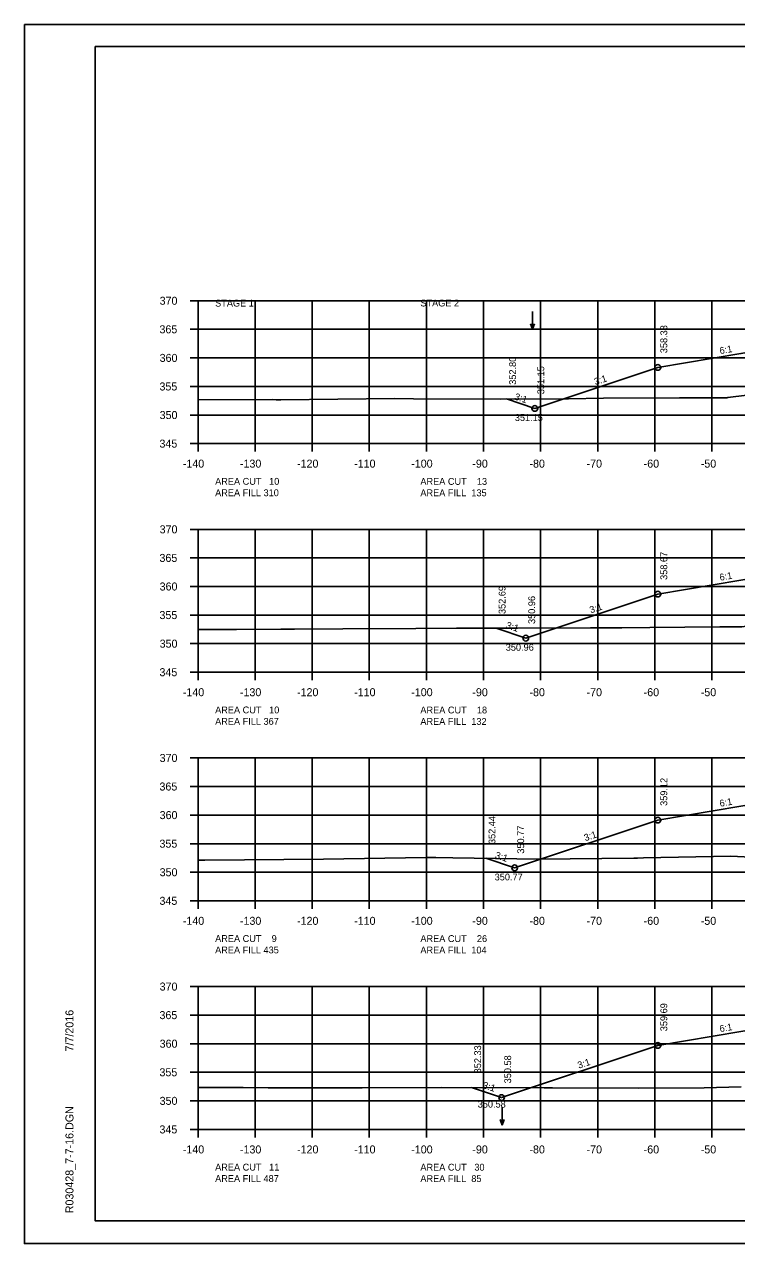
# Model space of a CAD drawing. Extents: x 1374859 to 1376773, y 382242 to 389804.
# Drawn here: x 1375964.2 to 1376088.9, y 386295.2 to 386508.5 of the extents above; entities that cross this region are included whole.
import ezdxf

# ---------------------------------------------------------------- set-up
doc = ezdxf.new("R2010")
doc.units = 0
for name, color, linetype in [('R_Axis', 7, 'Continuous'), ('R_Axis Annot', 7, 'Continuous'), ('R_Border', 7, 'Continuous'), ('R_Exist Surface', 7, 'Continuous'), ('R_Fin Surface', 7, 'Continuous'), ('R_Grid', 7, 'Continuous'), ('R_No Plot', 7, 'Continuous'), ('R_Water Annot', 7, 'Continuous'), ('R_Xsect Elev', 7, 'Continuous'), ('R_Xsect Slope', 7, 'Continuous')]:
    doc.layers.add(name, color=color, linetype=linetype)

msp = doc.modelspace()

# ---------------------------------------------------------------- linework, layer by layer
at = {"layer": 'R_Axis'}
for p, q in [((1375993.17, 386460.14), (1375994.57, 386460.14)), ((1375994.57, 386435.14), (1375994.57, 386460.14)), ((1375993.17, 386455.14), (1375994.57, 386455.14)), ((1375993.17, 386450.14), (1375994.57, 386450.14)), ((1375993.17, 386445.14), (1375994.57, 386445.14)), ((1375993.17, 386440.14), (1375994.57, 386440.14)), ((1375993.17, 386435.14), (1375994.57, 386435.14)), ((1375994.57, 386435.14), (1376274.57, 386435.14)), ((1375994.57, 386433.74), (1375994.57, 386435.14)), ((1376004.57, 386433.74), (1376004.57, 386435.14)), ((1376014.57, 386433.74), (1376014.57, 386435.14)), ((1376024.57, 386433.74), (1376024.57, 386435.14)), ((1376034.57, 386433.74), (1376034.57, 386435.14)), ((1376044.57, 386433.74), (1376044.57, 386435.14)), ((1376054.57, 386433.74), (1376054.57, 386435.14)), ((1376064.57, 386433.74), (1376064.57, 386435.14)), ((1376074.57, 386433.74), (1376074.57, 386435.14)), ((1376084.57, 386433.74), (1376084.57, 386435.14)), ((1375993.17, 386420.14), (1375994.57, 386420.14)), ((1375994.57, 386395.14), (1375994.57, 386420.14)), ((1375993.17, 386415.14), (1375994.57, 386415.14)), ((1375993.17, 386410.14), (1375994.57, 386410.14)), ((1375993.17, 386405.14), (1375994.57, 386405.14)), ((1375993.17, 386400.14), (1375994.57, 386400.14)), ((1375993.17, 386395.14), (1375994.57, 386395.14)), ((1375994.57, 386395.14), (1376274.57, 386395.14)), ((1375994.57, 386393.74), (1375994.57, 386395.14)), ((1376004.57, 386393.74), (1376004.57, 386395.14)), ((1376014.57, 386393.74), (1376014.57, 386395.14)), ((1376024.57, 386393.74), (1376024.57, 386395.14)), ((1376034.57, 386393.74), (1376034.57, 386395.14)), ((1376044.57, 386393.74), (1376044.57, 386395.14)), ((1376054.57, 386393.74), (1376054.57, 386395.14)), ((1376064.57, 386393.74), (1376064.57, 386395.14)), ((1376074.57, 386393.74), (1376074.57, 386395.14)), ((1376084.57, 386393.74), (1376084.57, 386395.14)), ((1375993.17, 386380.14), (1375994.57, 386380.14)), ((1375994.57, 386355.14), (1375994.57, 386380.14)), ((1375993.17, 386375.14), (1375994.57, 386375.14)), ((1375993.17, 386370.14), (1375994.57, 386370.14)), ((1375993.17, 386365.14), (1375994.57, 386365.14)), ((1375993.17, 386360.14), (1375994.57, 386360.14)), ((1375993.17, 386355.14), (1375994.57, 386355.14)), ((1375994.57, 386355.14), (1376274.57, 386355.14)), ((1375994.57, 386353.74), (1375994.57, 386355.14)), ((1376004.57, 386353.74), (1376004.57, 386355.14)), ((1376014.57, 386353.74), (1376014.57, 386355.14)), ((1376024.57, 386353.74), (1376024.57, 386355.14)), ((1376034.57, 386353.74), (1376034.57, 386355.14)), ((1376044.57, 386353.74), (1376044.57, 386355.14)), ((1376054.57, 386353.74), (1376054.57, 386355.14)), ((1376064.57, 386353.74), (1376064.57, 386355.14)), ((1376074.57, 386353.74), (1376074.57, 386355.14)), ((1376084.57, 386353.74), (1376084.57, 386355.14)), ((1375993.17, 386340.14), (1375994.57, 386340.14)), ((1375994.57, 386315.14), (1375994.57, 386340.14)), ((1375993.17, 386335.14), (1375994.57, 386335.14)), ((1375993.17, 386330.14), (1375994.57, 386330.14)), ((1375993.17, 386325.14), (1375994.57, 386325.14)), ((1375993.17, 386320.14), (1375994.57, 386320.14)), ((1375993.17, 386315.14), (1375994.57, 386315.14)), ((1375994.57, 386315.14), (1376274.57, 386315.14)), ((1375994.57, 386313.74), (1375994.57, 386315.14)), ((1376004.57, 386313.74), (1376004.57, 386315.14)), ((1376014.57, 386313.74), (1376014.57, 386315.14)), ((1376024.57, 386313.74), (1376024.57, 386315.14)), ((1376034.57, 386313.74), (1376034.57, 386315.14)), ((1376044.57, 386313.74), (1376044.57, 386315.14)), ((1376054.57, 386313.74), (1376054.57, 386315.14)), ((1376064.57, 386313.74), (1376064.57, 386315.14)), ((1376074.57, 386313.74), (1376074.57, 386315.14)), ((1376084.57, 386313.74), (1376084.57, 386315.14))]:
    msp.add_line(p, q, dxfattribs=at)
at = {"layer": 'R_Border'}
for p, q in [((1375976.57, 386504.6), (1376292.75, 386504.6)), ((1375976.57, 386299.14), (1375976.57, 386504.6)), ((1375976.57, 386299.14), (1375976.57, 386299.14)), ((1376292.75, 386299.14), (1375976.57, 386299.14))]:
    msp.add_line(p, q, dxfattribs=at)
at = {"layer": 'R_Exist Surface'}
for points in [[(1375994.57, 386442.8), (1376007.7, 386442.84), (1376008.26, 386442.83), (1376009.05, 386442.83), (1376029.01, 386443.01), (1376032.33, 386442.98), (1376047.5, 386442.94), (1376059.44, 386442.96), (1376065.56, 386443.09), (1376078.87, 386443.14), (1376082.7, 386443.16), (1376085.49, 386443.17), (1376086.97, 386443.17), (1376087.2, 386443.17), (1376087.37, 386443.2), (1376090.65, 386443.6), (1376091.79, 386443.74), (1376092.36, 386443.81), (1376092.66, 386443.84), (1376092.86, 386443.86)], [(1375994.57, 386402.62), (1376001.33, 386402.64), (1376009.06, 386402.67), (1376011.46, 386402.68), (1376019.91, 386402.72), (1376032.69, 386402.78), (1376039.85, 386402.82), (1376050.5, 386402.85), (1376063.28, 386402.91), (1376068.8, 386402.93), (1376073.68, 386402.96), (1376085.94, 386403.06), (1376089.36, 386403.09), (1376089.82, 386403.08), (1376090.21, 386403.12), (1376092.67, 386403.41), (1376093.97, 386403.51), (1376094.47, 386403.55), (1376094.67, 386403.56)], [(1375994.57, 386362.28), (1375995.79, 386362.28), (1376016.54, 386362.43), (1376034.45, 386362.71), (1376036.21, 386362.74), (1376039.18, 386362.69), (1376054.16, 386362.42), (1376070.87, 386362.62), (1376071.54, 386362.63), (1376072.61, 386362.64), (1376087.89, 386362.93), (1376091.4, 386362.75)], [(1375994.57, 386322.45), (1375995.79, 386322.45), (1376000.97, 386322.46), (1376002.5, 386322.46), (1376006.83, 386322.44), (1376018.73, 386322.39), (1376023.3, 386322.42), (1376037.22, 386322.49), (1376055.18, 386322.42), (1376055.99, 386322.42), (1376056.62, 386322.42), (1376071.78, 386322.35), (1376083.22, 386322.42), (1376089.68, 386322.58)]]:
    msp.add_lwpolyline(points, dxfattribs=at)
at = {"layer": 'R_Fin Surface'}
for points in [[(1376048.6, 386442.95), (1376053.55, 386441.3), (1376075.09, 386448.48), (1376089.65, 386450.9), (1376097.09, 386452.14), (1376105.09, 386452.46), (1376134.59, 386453.05), (1376164.09, 386452.46), (1376172.09, 386452.14), (1376179.52, 386450.9), (1376194.09, 386448.48), (1376212.49, 386442.34), (1376218.21, 386444.25)], [(1376046.76, 386402.84), (1376051.96, 386401.1), (1376075.09, 386408.81), (1376089.65, 386411.24), (1376097.09, 386412.48), (1376105.09, 386412.8), (1376134.59, 386413.39), (1376164.09, 386412.8), (1376172.09, 386412.48), (1376179.52, 386411.24), (1376194.09, 386408.81), (1376214.1, 386402.14), (1376220.65, 386404.32)], [(1376045, 386362.59), (1376050.02, 386360.91), (1376075.09, 386369.27), (1376089.65, 386371.7), (1376097.09, 386372.93), (1376105.09, 386373.25), (1376134.59, 386373.84), (1376164.09, 386373.25), (1376172.09, 386372.93), (1376179.52, 386371.7), (1376194.09, 386369.27), (1376217.23, 386361.55), (1376224.5, 386363.98)], [(1376042.49, 386322.47), (1376047.74, 386320.72), (1376075.09, 386329.83), (1376089.65, 386332.26), (1376097.09, 386333.5), (1376105.09, 386333.82), (1376134.59, 386334.41), (1376164.09, 386333.82), (1376172.09, 386333.5), (1376179.52, 386332.26), (1376194.09, 386329.83), (1376220.7, 386320.96), (1376227.96, 386323.38)]]:
    msp.add_lwpolyline(points, dxfattribs=at)
at = {"layer": 'R_Grid'}
for p, q in [((1375994.57, 386460.14), (1376274.57, 386460.14)), ((1375994.57, 386435.14), (1375994.57, 386460.14)), ((1376004.57, 386435.14), (1376004.57, 386460.14)), ((1376014.57, 386435.14), (1376014.57, 386460.14)), ((1376024.57, 386435.14), (1376024.57, 386460.14)), ((1376034.57, 386435.14), (1376034.57, 386460.14)), ((1376044.57, 386435.14), (1376044.57, 386460.14)), ((1376054.57, 386435.14), (1376054.57, 386460.14)), ((1376064.57, 386435.14), (1376064.57, 386460.14)), ((1376074.57, 386435.14), (1376074.57, 386460.14)), ((1376084.57, 386435.14), (1376084.57, 386460.14)), ((1375994.57, 386455.14), (1376274.57, 386455.14)), ((1375994.57, 386450.14), (1376274.57, 386450.14)), ((1375994.57, 386445.14), (1376274.57, 386445.14)), ((1375994.57, 386440.14), (1376274.57, 386440.14)), ((1375994.57, 386435.14), (1376274.57, 386435.14)), ((1375994.57, 386420.14), (1376274.57, 386420.14)), ((1375994.57, 386395.14), (1375994.57, 386420.14)), ((1376004.57, 386395.14), (1376004.57, 386420.14)), ((1376014.57, 386395.14), (1376014.57, 386420.14)), ((1376024.57, 386395.14), (1376024.57, 386420.14)), ((1376034.57, 386395.14), (1376034.57, 386420.14)), ((1376044.57, 386395.14), (1376044.57, 386420.14)), ((1376054.57, 386395.14), (1376054.57, 386420.14)), ((1376064.57, 386395.14), (1376064.57, 386420.14)), ((1376074.57, 386395.14), (1376074.57, 386420.14)), ((1376084.57, 386395.14), (1376084.57, 386420.14)), ((1375994.57, 386415.14), (1376274.57, 386415.14)), ((1375994.57, 386410.14), (1376274.57, 386410.14)), ((1375994.57, 386405.14), (1376274.57, 386405.14)), ((1375994.57, 386400.14), (1376274.57, 386400.14)), ((1375994.57, 386395.14), (1376274.57, 386395.14)), ((1375994.57, 386380.14), (1376274.57, 386380.14)), ((1375994.57, 386355.14), (1375994.57, 386380.14)), ((1376004.57, 386355.14), (1376004.57, 386380.14)), ((1376014.57, 386355.14), (1376014.57, 386380.14)), ((1376024.57, 386355.14), (1376024.57, 386380.14)), ((1376034.57, 386355.14), (1376034.57, 386380.14)), ((1376044.57, 386355.14), (1376044.57, 386380.14)), ((1376054.57, 386355.14), (1376054.57, 386380.14)), ((1376064.57, 386355.14), (1376064.57, 386380.14)), ((1376074.57, 386355.14), (1376074.57, 386380.14)), ((1376084.57, 386355.14), (1376084.57, 386380.14)), ((1375994.57, 386375.14), (1376274.57, 386375.14)), ((1375994.57, 386370.14), (1376274.57, 386370.14)), ((1375994.57, 386365.14), (1376274.57, 386365.14)), ((1375994.57, 386360.14), (1376274.57, 386360.14)), ((1375994.57, 386355.14), (1376274.57, 386355.14)), ((1375994.57, 386340.14), (1376274.57, 386340.14)), ((1375994.57, 386315.14), (1375994.57, 386340.14)), ((1376004.57, 386315.14), (1376004.57, 386340.14)), ((1376014.57, 386315.14), (1376014.57, 386340.14)), ((1376024.57, 386315.14), (1376024.57, 386340.14)), ((1376034.57, 386315.14), (1376034.57, 386340.14)), ((1376044.57, 386315.14), (1376044.57, 386340.14)), ((1376054.57, 386315.14), (1376054.57, 386340.14)), ((1376064.57, 386315.14), (1376064.57, 386340.14)), ((1376074.57, 386315.14), (1376074.57, 386340.14)), ((1376084.57, 386315.14), (1376084.57, 386340.14)), ((1375994.57, 386335.14), (1376274.57, 386335.14)), ((1375994.57, 386330.14), (1376274.57, 386330.14)), ((1375994.57, 386325.14), (1376274.57, 386325.14)), ((1375994.57, 386320.14), (1376274.57, 386320.14)), ((1375994.57, 386315.14), (1376274.57, 386315.14))]:
    msp.add_line(p, q, dxfattribs=at)
at = {"layer": 'R_No Plot'}
for p, q in [((1375964.17, 386508.5), (1376297.5, 386508.5)), ((1375964.17, 386295.16), (1376297.5, 386295.16))]:
    msp.add_line(p, q, dxfattribs=at)
for points in [[(1375964.16, 386508.5), (1376297.5, 386508.5), (1376297.5, 386295.16), (1375964.16, 386295.16)], [(1376210.49, 386504.6), (1376210.49, 386494.72), (1376246.22, 386494.72), (1376246.22, 386491.8), (1376269.42, 386491.8), (1376269.42, 386467.47), (1376292.75, 386467.47), (1376292.75, 386299.14), (1375976.57, 386299.14), (1375976.57, 386504.6)]]:
    msp.add_lwpolyline(points, close=True, dxfattribs=at)
for centre in [(1376075.09, 386448.48), (1376053.55, 386441.3), (1376075.09, 386408.81), (1376051.96, 386401.1), (1376075.09, 386369.27), (1376050.02, 386360.91), (1376075.09, 386329.83), (1376047.74, 386320.72)]:
    msp.add_circle(centre, 0.5, dxfattribs=at)
at = {"layer": 'R_Water Annot'}
for p, q in [((1376053.12, 386458.28), (1376053.12, 386455.14)), ((1376053.12, 386455.14), (1376052.77, 386456.1)), ((1376053.12, 386455.14), (1376053.47, 386456.1)), ((1376047.84, 386319.05), (1376047.84, 386315.91)), ((1376047.84, 386315.91), (1376047.49, 386316.87)), ((1376047.84, 386315.91), (1376048.19, 386316.87))]:
    msp.add_line(p, q, dxfattribs=at)

# ---------------------------------------------------------------- texts
at = {"layer": 'R_Axis Annot'}
for s, height, p in [('370', 1.4, (1375987.85, 386459.44)), ('365', 1.4, (1375987.82, 386454.44)), ('360', 1.4, (1375987.85, 386449.44)), ('355', 1.4, (1375987.82, 386444.44)), ('350', 1.4, (1375987.85, 386439.44)), ('345', 1.4, (1375987.82, 386434.44)), ('-140', 1.4, (1375991.91, 386430.94)), ('-130', 1.4, (1376001.91, 386430.94)), ('-120', 1.4, (1376011.91, 386430.94)), ('-110', 1.4, (1376021.91, 386430.94)), ('-100', 1.4, (1376031.91, 386430.94)), ('-90', 1.4, (1376042.61, 386430.94)), ('-80', 1.4, (1376052.61, 386430.94)), ('-70', 1.4, (1376062.61, 386430.94)), ('-60', 1.4, (1376072.61, 386430.94)), ('-50', 1.4, (1376082.61, 386430.94)), ('AREA CUT   10', 1.2, (1375997.57, 386427.94)), ('AREA CUT    13', 1.2, (1376033.51, 386427.93)), ('AREA FILL 310', 1.2, (1375997.57, 386425.94)), ('AREA FILL  135', 1.2, (1376033.51, 386425.93)), ('370', 1.4, (1375987.85, 386419.44)), ('365', 1.4, (1375987.82, 386414.44)), ('360', 1.4, (1375987.85, 386409.44)), ('355', 1.4, (1375987.82, 386404.44)), ('350', 1.4, (1375987.85, 386399.44)), ('345', 1.4, (1375987.82, 386394.44)), ('-140', 1.4, (1375991.91, 386390.94)), ('-130', 1.4, (1376001.91, 386390.94)), ('-120', 1.4, (1376011.91, 386390.94)), ('-110', 1.4, (1376021.91, 386390.94)), ('-100', 1.4, (1376031.91, 386390.94)), ('-90', 1.4, (1376042.61, 386390.94)), ('-80', 1.4, (1376052.61, 386390.94)), ('-70', 1.4, (1376062.61, 386390.94)), ('-60', 1.4, (1376072.61, 386390.94)), ('-50', 1.4, (1376082.61, 386390.94)), ('AREA CUT   10', 1.2, (1375997.57, 386387.94)), ('AREA CUT    18', 1.2, (1376033.51, 386387.93)), ('AREA FILL 367', 1.2, (1375997.57, 386385.94)), ('AREA FILL  132', 1.2, (1376033.51, 386385.93)), ('370', 1.4, (1375987.85, 386379.44)), ('365', 1.4, (1375987.82, 386374.44)), ('360', 1.4, (1375987.85, 386369.44)), ('355', 1.4, (1375987.82, 386364.44)), ('350', 1.4, (1375987.85, 386359.44)), ('345', 1.4, (1375987.82, 386354.44)), ('-140', 1.4, (1375991.91, 386350.94)), ('-130', 1.4, (1376001.91, 386350.94)), ('-120', 1.4, (1376011.91, 386350.94)), ('-110', 1.4, (1376021.91, 386350.94)), ('-100', 1.4, (1376031.91, 386350.94)), ('-90', 1.4, (1376042.61, 386350.94)), ('-80', 1.4, (1376052.61, 386350.94)), ('-70', 1.4, (1376062.61, 386350.94)), ('-60', 1.4, (1376072.61, 386350.94)), ('-50', 1.4, (1376082.61, 386350.94)), ('AREA CUT    9', 1.2, (1375997.57, 386347.94)), ('AREA CUT    26', 1.2, (1376033.51, 386347.93)), ('AREA FILL 435', 1.2, (1375997.57, 386345.94)), ('AREA FILL  104', 1.2, (1376033.51, 386345.93)), ('370', 1.4, (1375987.85, 386339.44)), ('365', 1.4, (1375987.82, 386334.44)), ('360', 1.4, (1375987.85, 386329.44)), ('355', 1.4, (1375987.82, 386324.44)), ('350', 1.4, (1375987.85, 386319.44)), ('345', 1.4, (1375987.82, 386314.44)), ('-140', 1.4, (1375991.91, 386310.94)), ('-130', 1.4, (1376001.91, 386310.94)), ('-120', 1.4, (1376011.91, 386310.94)), ('-110', 1.4, (1376021.91, 386310.94)), ('-100', 1.4, (1376031.91, 386310.94)), ('-90', 1.4, (1376042.61, 386310.94)), ('-80', 1.4, (1376052.61, 386310.94)), ('-70', 1.4, (1376062.61, 386310.94)), ('-60', 1.4, (1376072.61, 386310.94)), ('-50', 1.4, (1376082.61, 386310.94)), ('AREA CUT   11', 1.2, (1375997.57, 386307.94)), ('AREA CUT   30', 1.2, (1376033.51, 386307.93)), ('AREA FILL 487', 1.2, (1375997.57, 386305.94)), ('AREA FILL  85', 1.2, (1376033.51, 386305.93))]:
    msp.add_text(s, height=height, dxfattribs=at).set_placement(p)
for s, p in [('STAGE 1', (1375997.57, 386459.12)), ('STAGE 2', (1376033.51, 386459.14))]:
    msp.add_text(s, height=1.2, rotation=360, dxfattribs=at).set_placement(p)
at = {"layer": 'R_Border'}
for s, p in [('7/7/2016', (1375972.76, 386328.78)), ('R030428_7-7-16.DGN', (1375972.76, 386300.47))]:
    msp.add_text(s, height=1.4, rotation=90, dxfattribs=at).set_placement(p)
at = {"layer": 'R_Xsect Elev'}
for s, p in [('358.33', (1376076.74, 386450.96)), ('352.80', (1376050.26, 386445.43)), ('351.15', (1376055.2, 386443.78)), ('358.67', (1376076.74, 386411.29)), ('352.69', (1376048.42, 386405.32)), ('350.96', (1376053.61, 386403.58)), ('359.12', (1376076.74, 386371.75)), ('352.44', (1376046.65, 386365.07)), ('350.77', (1376051.68, 386363.39)), ('359.69', (1376076.74, 386332.32)), ('352.33', (1376044.14, 386324.95)), ('350.58', (1376049.4, 386323.2))]:
    msp.add_text(s, height=1.2, rotation=90, dxfattribs=at).set_placement(p)
for s, p in [('351.15', (1376050.05, 386439.1)), ('350.96', (1376048.46, 386398.9)), ('350.77', (1376046.52, 386358.71)), ('350.58', (1376043.55, 386318.96))]:
    msp.add_text(s, height=1.2, dxfattribs=at).set_placement(p)
at = {"layer": 'R_Xsect Slope'}
for s, rotation, p in [('6:1', 9.4642, (1376086, 386450.8)), ('3:1', 18.4349, (1376064.16, 386445.36)), ('3:1', 341.5651, (1376049.88, 386442.88)), ('6:1', 9.4642, (1376086, 386411.14)), ('3:1', 18.4349, (1376063.36, 386405.43)), ('3:1', 341.5651, (1376048.39, 386402.88)), ('6:1', 9.4642, (1376086, 386371.59)), ('3:1', 18.4349, (1376062.39, 386365.56)), ('3:1', 341.5651, (1376046.48, 386362.64)), ('6:1', 9.4642, (1376086, 386332.16)), ('3:1', 18.4349, (1376061.26, 386325.75)), ('3:1', 341.5651, (1376044.31, 386322.41))]:
    msp.add_text(s, height=1.2, rotation=rotation, dxfattribs=at).set_placement(p)

doc.saveas('drawing.dxf')
